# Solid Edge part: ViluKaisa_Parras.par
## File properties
Author: kaisa
Template: Iso Metric Part.par
Last saved by: kaisa
Revision: 20
Application: Solid Edge
Density: 7750.000 kg/m^3
Accuracy: 0.990
Username: kaisa
Material: Stainless steel
Face Style: Teal
Fill Style: ANSI32(Steel)
Virtual Style: ANSI32(Steel)
Grouping: Metals\Steel
LibraryName: Materials
Coef. of Thermal Exp: 1.6e-05
Thermal Conductivity: 17.0
Specific Heat: 502.0
Modulus of Elasticity: 193053196000.0
Poisson's Ratio: 0.29
Yield Stress: 310264065.0
Ultimate Stress: 641212401.0
Elongation: 0.0
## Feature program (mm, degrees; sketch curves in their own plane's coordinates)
make body feature "unnamed MakeBodyFeature 1"
thinwall "Thinwall_2"  Thickness = 3 mm
web network "WebNetwork_1"  Thickness = 3 mm
sketch for "ExtrudedProtrusion_1" plane through (0, 0, 29.7245) normal (0, 1, 0) x-axis (-1, 0, 0)
extrude "ExtrudedProtrusion_1" add finite 10 along +normal
sketch for "ExtrudedCutout_2" plane through (0, -35.8921, 53.2931) normal (0, 0, 1) x-axis (1, 0, 0)
  circle centre (0, 41.095) radius 3
extrude "ExtrudedCutout_2" cut finite 2.5 along -normal
sketch for "ExtrudedCutout_3" plane through (0, -35.8921, 53.2931) normal (0, 0, 1) x-axis (1, 0, 0)
  circle centre (74.8125, 41.095) radius 3
extrude "ExtrudedCutout_3" cut finite 2.5 along -normal
sketch for "ExtrudedCutout_4" plane through (0, -40, 55.2831) normal (0, 0.032061, 0.999486) x-axis (1, 0, 0)
  circle centre (-134.375, 37.1405) radius 1
extrude "ExtrudedCutout_4" cut finite 1 along -normal
pattern "unnamed Pattern 1" of "ExtrudedCutout_4"
pattern "Pattern_3" along a curve  XDirCount = 8; XDirSpacing = 45 mm
Other named dimensions: "KeypointCurve_6": StartDerivMagnitude = 120.8573 mm; EndDerivMagnitude = -120.8573 mm
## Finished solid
Body 1: solid body, 30 faces, 44 edges, 16 vertices.
  Faces by surface: plane 15, cylinder 10, offset 2, swept 2, spline 1
  Edges by curve: circle 20, line 10, intersection 6, spline 6, curve on surface 2
Body 2: solid body, 3 faces, 5 edges, 4 vertices.
  Faces by surface: plane 2, spline 1
  Edges by curve: curve on surface 2, spline 2, line 1
Bounding box of the edges (mm; curved faces can reach further): 279.950 x 90.000 x 50.582, from (-139.9748, -80, 5.9842) to (139.9748, 10, 56.5662).
Cylindrical faces by radius (mm): R1 x8, R3 x2
Planar faces by outward normal: +y 3, +z 3, -z 1, oblique 10
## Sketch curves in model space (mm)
spline (-134.375, -2.8786, 54.0923) -> (-0.026, -78.6948, 56.5244) -> (134.315, -2.8786, 54.0923)
line (45.1014, 0, 51.7931) -> (-40.8485, 0, 51.7931)
spline (0, -80, 56.5662) -> (0, -57.2548, 19.9266) -> (0, 0, 6.36)
spline (-139.9748, 0, 54) -> (-129.3002, 0, 27.0039) -> (-114.8194, 0, 12.3978)
spline (139.9748, 0, 54) -> (129.3002, 0, 27.0039) -> (114.8194, 0, 12.3978)
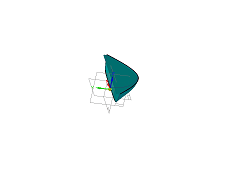
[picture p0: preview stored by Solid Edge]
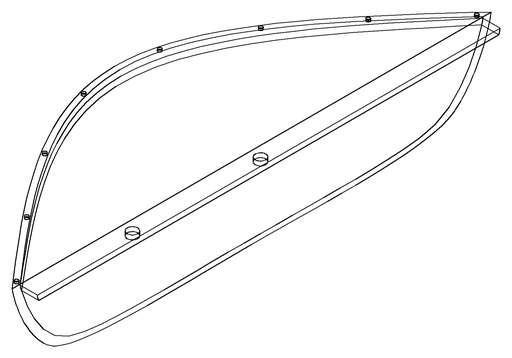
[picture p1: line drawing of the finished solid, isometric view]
